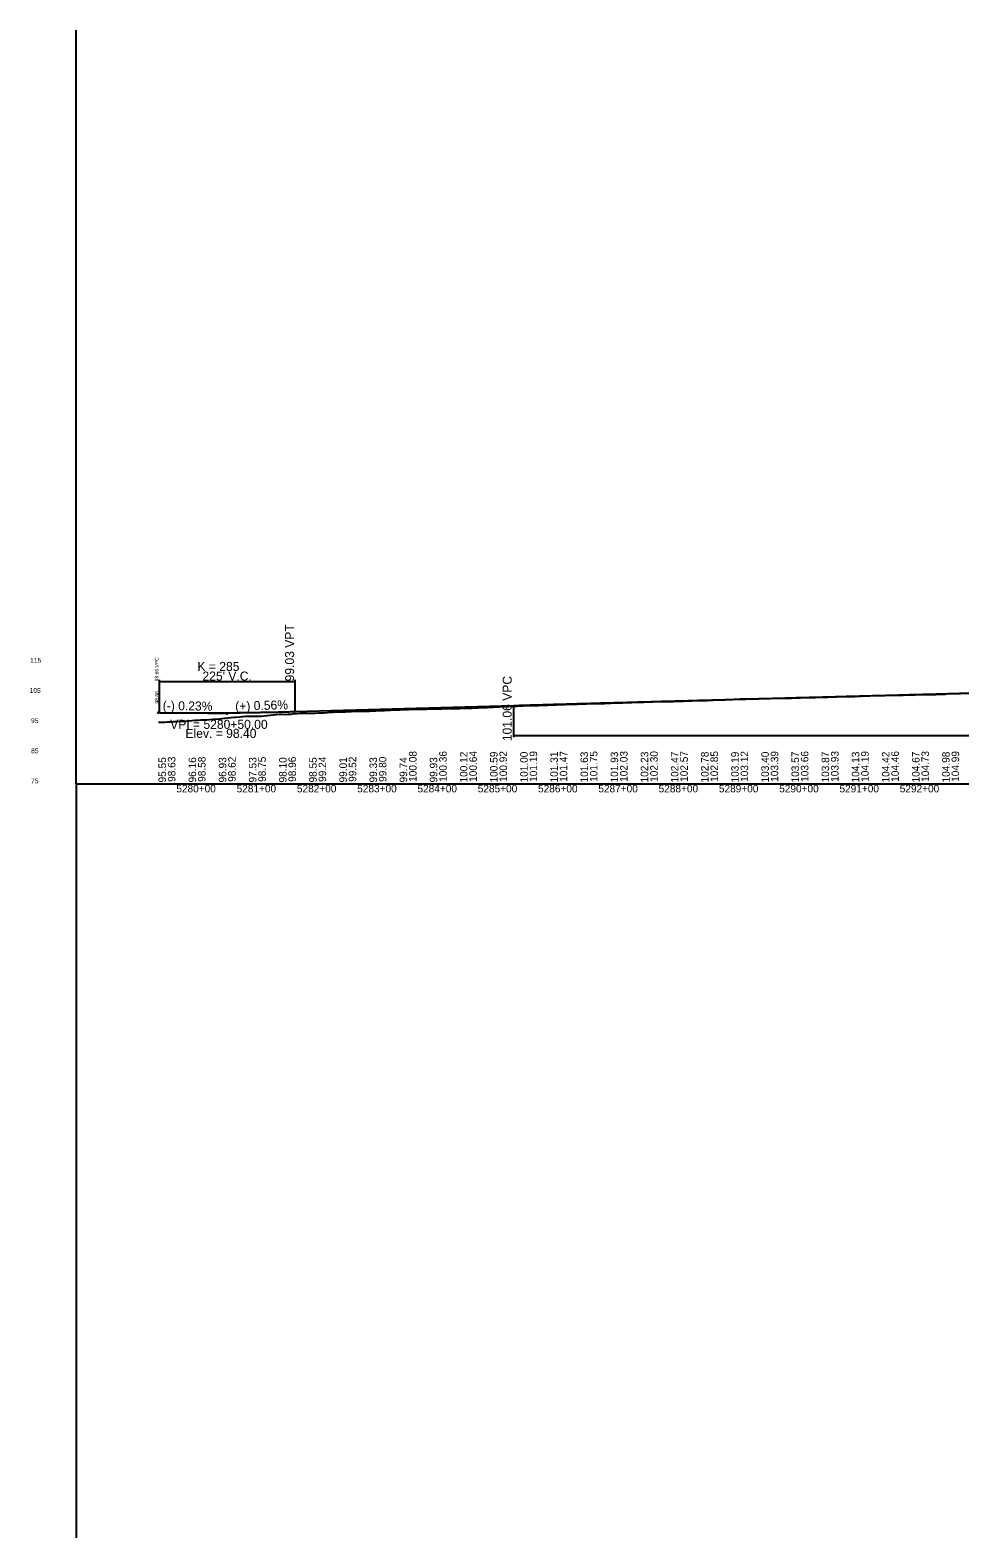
# Model space of a CAD drawing. Extents: x 2121671 to 2169879, y 557274 to 599957.
# Drawn here: x 2157292 to 2158834, y 591457 to 593957 of the extents above; entities that cross this region are included whole.
import ezdxf

# ---------------------------------------------------------------- set-up
doc = ezdxf.new("R2010")
doc.units = 0
for name, color, linetype in [('RD_DDB_ElevTX', 7, 'Continuous'), ('RD_DDB_GradeTX', 7, 'Continuous'), ('RD_DDB_Profile_EX', 7, 'Continuous'), ('RD_DDB_Profile_Lbl', 7, 'Continuous'), ('RD_DDB_Profile_PR', 7, 'Continuous'), ('RD_DDB_StaTX', 7, 'Continuous'), ('RD_DDB_StripGrade', 7, 'Continuous'), ('RD_DDB_VCLbl', 7, 'Continuous'), ('RD_GPK_Profile_Cell', 7, 'Continuous')]:
    doc.layers.add(name, color=color, linetype=linetype)

msp = doc.modelspace()

# ---------------------------------------------------------------- linework, layer by layer
at = {"layer": 'RD_DDB_GradeTX'}
for p, q in [((2157556.2, 592825.2), (2157617.2, 592824.5)), ((2157680.2, 592826.2), (2157619.2, 592824.5))]:
    msp.add_line(p, q, dxfattribs=at)
for centre in [(2157504.8, 592825.8), (2157618.2, 592824.5)]:
    msp.add_circle(centre, 1, dxfattribs=at)
at = {"layer": 'RD_DDB_Profile_EX'}
for points in [[(2158504.8, 592849.1), (2158509.8, 592849.2), (2158514.8, 592849.3), (2158519.8, 592849.5), (2158524.8, 592849.7), (2158529.8, 592849.8), (2158534.8, 592849.8), (2158539.8, 592849.8), (2158544.8, 592850), (2158549.8, 592850), (2158554.8, 592850), (2158559.8, 592850.1), (2158564.8, 592850.2), (2158569.8, 592850.4), (2158574.8, 592850.8), (2158579.8, 592850.9), (2158584.8, 592850.9), (2158589.8, 592851), (2158594.8, 592851.1), (2158599.8, 592851.3), (2158604.8, 592851.4), (2158609.8, 592851.5), (2158614.8, 592851.7), (2158619.8, 592851.9), (2158624.8, 592852), (2158629.8, 592852.2), (2158634.8, 592852.3), (2158639.8, 592852.4), (2158644.8, 592852.5), (2158649.8, 592852.6), (2158654.8, 592852.7), (2158659.8, 592852.8), (2158664.8, 592853), (2158669.8, 592853.2), (2158674.8, 592853.4), (2158679.8, 592853.5), (2158684.8, 592853.6), (2158689.8, 592854), (2158694.8, 592854.3), (2158699.8, 592854.5), (2158704.8, 592854.3), (2158709.8, 592854.4), (2158714.8, 592854.5), (2158719.8, 592854.6), (2158724.8, 592854.6), (2158729.8, 592854.8), (2158734.8, 592854.7), (2158739.8, 592855), (2158744.8, 592855.2), (2158749.8, 592855.1), (2158754.8, 592854.9), (2158759.8, 592855.3), (2158764.8, 592855.7), (2158769.8, 592855.9), (2158774.8, 592855.9), (2158779.8, 592856), (2158784.8, 592856), (2158789.8, 592856.1), (2158794.8, 592856.1), (2158799.8, 592856.2), (2158804.8, 592856.4), (2158809.8, 592856.5), (2158814.8, 592857.3), (2158819.8, 592857.4), (2158824.8, 592857.6), (2158829.8, 592857.7), (2158834.8, 592857.8)], [(2157504.8, 592810), (2157509.8, 592810.2), (2157514.8, 592810), (2157519.8, 592810.3), (2157524.8, 592810.6), (2157529.8, 592810.9), (2157534.8, 592811.2), (2157539.8, 592811.4), (2157544.8, 592811.5), (2157549.8, 592811.9), (2157554.8, 592812.2), (2157559.8, 592812.8), (2157564.8, 592813.1), (2157569.8, 592813.4), (2157574.8, 592813.7), (2157579.8, 592813.9), (2157584.8, 592814), (2157589.8, 592814.3), (2157594.8, 592814.9), (2157599.8, 592815.1), (2157604.8, 592815.5), (2157609.8, 592816.2), (2157614.8, 592816.9), (2157619.8, 592817.2), (2157624.8, 592817.6), (2157629.8, 592818.1), (2157634.8, 592818.4), (2157639.8, 592818.7), (2157644.8, 592819.4), (2157649.8, 592819.7), (2157654.8, 592819.9), (2157659.8, 592820), (2157664.8, 592820), (2157669.8, 592820.2), (2157674.8, 592820.2), (2157679.8, 592820.4), (2157684.8, 592821.1), (2157689.8, 592821.6), (2157694.8, 592822.1), (2157699.8, 592822.7), (2157704.8, 592823.2), (2157709.8, 592823), (2157714.8, 592822.9), (2157719.8, 592823), (2157724.8, 592823.5), (2157729.8, 592824.1), (2157734.8, 592824.5), (2157739.8, 592824.7), (2157744.8, 592824.8), (2157749.8, 592824.9), (2157754.8, 592825), (2157759.8, 592825), (2157764.8, 592825.1), (2157769.8, 592825.3), (2157774.8, 592825.4), (2157779.8, 592825.7), (2157784.8, 592826), (2157789.8, 592826.4), (2157794.8, 592826.6), (2157799.8, 592826.9), (2157804.8, 592827), (2157809.8, 592827.2), (2157814.8, 592827.4), (2157819.8, 592827.6), (2157824.8, 592827.8), (2157829.8, 592828), (2157834.8, 592828.2), (2157839.8, 592828.2), (2157844.8, 592828.3), (2157849.8, 592828.4), (2157854.8, 592828.5), (2157859.8, 592828.7), (2157864.8, 592829), (2157869.8, 592829.2), (2157874.8, 592829.4), (2157879.8, 592829.6), (2157884.8, 592829.7), (2157889.8, 592829.9), (2157894.8, 592830.2), (2157899.8, 592830.5), (2157904.8, 592830.7), (2157909.8, 592830.9), (2157914.8, 592831.1), (2157919.8, 592831.2), (2157924.8, 592831.4), (2157929.8, 592831.5), (2157934.8, 592831.5), (2157939.8, 592831.6), (2157944.8, 592831.6), (2157949.8, 592831.7), (2157954.8, 592831.9), (2157959.8, 592832), (2157964.8, 592832), (2157969.8, 592832.1), (2157974.8, 592832.3), (2157979.8, 592832.4), (2157984.8, 592832.3), (2157989.8, 592832.5), (2157994.8, 592832.6), (2157999.8, 592832.8), (2158004.8, 592832.8)], [(2158004.8, 592832.8), (2158009.8, 592833), (2158014.8, 592833), (2158019.8, 592833.1), (2158024.8, 592833.3), (2158029.8, 592833.6), (2158034.8, 592833.8), (2158039.8, 592834.1), (2158044.8, 592834.4), (2158049.8, 592834.5), (2158054.8, 592834.8), (2158059.8, 592835), (2158064.8, 592835.3), (2158069.8, 592835.5), (2158074.8, 592835.8), (2158079.8, 592836), (2158084.8, 592836.1), (2158089.8, 592836.4), (2158094.8, 592836.6), (2158099.8, 592836.8), (2158104.8, 592837), (2158109.8, 592837.2), (2158114.8, 592837.4), (2158119.8, 592837.5), (2158124.8, 592837.6), (2158129.8, 592837.8), (2158134.8, 592837.9), (2158139.8, 592838), (2158144.8, 592838.1), (2158149.8, 592838.3), (2158154.8, 592838.5), (2158159.8, 592838.7), (2158164.8, 592838.9), (2158169.8, 592839.1), (2158174.8, 592839.2), (2158179.8, 592839.4), (2158184.8, 592839.6), (2158189.8, 592839.7), (2158194.8, 592839.9), (2158199.8, 592840.1), (2158204.8, 592840.3), (2158209.8, 592840.4), (2158214.8, 592840.5), (2158219.8, 592840.7), (2158224.8, 592840.8), (2158229.8, 592840.9), (2158234.8, 592841), (2158239.8, 592841.1), (2158244.8, 592841.2), (2158249.8, 592841.4), (2158254.8, 592841.7), (2158259.8, 592841.9), (2158264.8, 592842), (2158269.8, 592842.2), (2158274.8, 592842.3), (2158279.8, 592842.4), (2158284.8, 592842.5), (2158289.8, 592842.8), (2158294.8, 592843), (2158299.8, 592843.1), (2158304.8, 592843.2), (2158309.8, 592843.4), (2158314.8, 592843.5), (2158319.8, 592843.7), (2158324.8, 592843.8), (2158329.8, 592844), (2158334.8, 592844), (2158339.8, 592844.1), (2158344.8, 592844.1), (2158349.8, 592844.1), (2158354.8, 592844.3), (2158359.8, 592844.5), (2158364.8, 592844.7), (2158369.8, 592844.8), (2158374.8, 592844.9), (2158379.8, 592845.1), (2158384.8, 592845.3), (2158389.8, 592845.6), (2158394.8, 592845.7), (2158399.8, 592845.7), (2158404.8, 592845.8), (2158409.8, 592845.9), (2158414.8, 592846.1), (2158419.8, 592846.5), (2158424.8, 592846.6), (2158429.8, 592846.8), (2158434.8, 592847), (2158439.8, 592847.2), (2158444.8, 592847.3), (2158449.8, 592847.4), (2158454.8, 592847.6), (2158459.8, 592847.9), (2158464.8, 592848.2), (2158469.8, 592848.5), (2158474.8, 592848.6), (2158479.8, 592848.6), (2158484.8, 592848.6), (2158489.8, 592848.8), (2158494.8, 592848.9), (2158499.8, 592849), (2158504.8, 592849.1)]]:
    msp.add_lwpolyline(points, dxfattribs=at)
at = {"layer": 'RD_DDB_Profile_PR'}
for p, q in [((2157504.8, 592825.8), (2157505.7, 592825.8)), ((2157730.7, 592827.6), (2158094.2, 592837.8))]:
    msp.add_line(p, q, dxfattribs=at)
for points in [[(2158094.2, 592837.8), (2158129.2, 592838.7), (2158164.2, 592839.7), (2158199.2, 592840.7), (2158234.2, 592841.7), (2158269.2, 592842.6), (2158304.2, 592843.6), (2158339.2, 592844.6), (2158374.2, 592845.5), (2158409.2, 592846.5), (2158444.2, 592847.4), (2158479.2, 592848.4), (2158514.2, 592849.3), (2158549.2, 592850.3), (2158584.2, 592851.2), (2158619.2, 592852.1), (2158654.2, 592853.1), (2158689.2, 592854), (2158724.2, 592854.9), (2158759.2, 592855.9), (2158794.2, 592856.8), (2158829.2, 592857.7), (2158864.2, 592858.6), (2158899.2, 592859.5), (2158934.2, 592860.5), (2158969.2, 592861.4), (2159004.2, 592862.3), (2159039.2, 592863.2), (2159074.2, 592864.1), (2159109.2, 592865), (2159144.2, 592865.9), (2159179.2, 592866.8), (2159214.2, 592867.7), (2159249.2, 592868.5), (2159284.2, 592869.4), (2159319.2, 592870.3), (2159354.2, 592871.2), (2159389.2, 592872.1), (2159424.2, 592873), (2159459.2, 592873.8), (2159494.2, 592874.7), (2159529.2, 592875.6), (2159564.2, 592876.4), (2159599.2, 592877.3), (2159634.2, 592878.1), (2159669.2, 592879), (2159704.2, 592879.9), (2159739.2, 592880.7), (2159774.2, 592881.6), (2159809.2, 592882.4), (2159844.2, 592883.2)], [(2157505.7, 592825.8), (2157510.2, 592825.7), (2157514.7, 592825.7), (2157519.2, 592825.6), (2157523.7, 592825.6), (2157528.2, 592825.6), (2157532.7, 592825.5), (2157537.2, 592825.5), (2157541.7, 592825.5), (2157546.2, 592825.4), (2157550.7, 592825.4), (2157555.2, 592825.4), (2157559.7, 592825.4), (2157564.2, 592825.4), (2157568.7, 592825.4), (2157573.2, 592825.4), (2157577.7, 592825.4), (2157582.2, 592825.4), (2157586.7, 592825.4), (2157591.2, 592825.4), (2157595.7, 592825.4), (2157600.2, 592825.5), (2157604.7, 592825.5), (2157609.2, 592825.5), (2157613.7, 592825.5), (2157618.2, 592825.6), (2157622.7, 592825.6), (2157627.2, 592825.7), (2157631.7, 592825.7), (2157636.2, 592825.8), (2157640.7, 592825.8), (2157645.2, 592825.9), (2157649.7, 592825.9), (2157654.2, 592826), (2157658.7, 592826.1), (2157663.2, 592826.1), (2157667.7, 592826.2), (2157672.2, 592826.3), (2157676.7, 592826.4), (2157681.2, 592826.4), (2157685.7, 592826.5), (2157690.2, 592826.6), (2157694.7, 592826.7), (2157699.2, 592826.8), (2157703.7, 592826.9), (2157708.2, 592827), (2157712.7, 592827.1), (2157717.2, 592827.3), (2157721.7, 592827.4), (2157726.2, 592827.5), (2157730.7, 592827.6)]]:
    msp.add_spline(points, degree=3, dxfattribs=at)
at = {"layer": 'RD_DDB_VCLbl'}
for p, q in [((2157505.7, 592880.1), (2157505.7, 592825.8)), ((2157505.7, 592877.6), (2157730.7, 592877.6)), ((2157730.7, 592880.1), (2157730.7, 592827.6)), ((2158094.2, 592785.3), (2158094.2, 592837.8)), ((2158094.2, 592787.8), (2159844.2, 592787.8))]:
    msp.add_line(p, q, dxfattribs=at)
at = {"layer": 'RD_GPK_Profile_Cell'}
for q in [(2157368.2, 593957.5), (2160568.2, 592707.5), (2157368.2, 591457.5)]:
    msp.add_line((2157368.2, 592707.5), q, dxfattribs=at)

# ---------------------------------------------------------------- texts
at = {"layer": 'RD_DDB_ElevTX'}
for s, p in [('115', (2157291.8, 592908.5)), ('105', (2157291, 592858.5)), ('95', (2157293.4, 592808.5)), ('85', (2157293.4, 592758.5)), ('75', (2157293.4, 592708.5))]:
    msp.add_text(s, height=8, dxfattribs=at).set_placement(p)
at = {"layer": 'RD_DDB_GradeTX'}
for s, rotation, p in [('(-) 0.23%', 359.3411, (2157511.7, 592830)), ('(+) 0.56%', 1.6002, (2157632.2, 592829))]:
    msp.add_text(s, height=15, rotation=rotation, dxfattribs=at).set_placement(p)
at = {"layer": 'RD_DDB_Profile_Lbl'}
msp.add_text('98.66', height=6, rotation=90, dxfattribs=at).set_placement((2157504.8, 592840.8))
for s, p in [('VPI = 5280+50.00', (2157524.1, 592798.9)), ('Elev. = 98.40', (2157549.5, 592783.9))]:
    msp.add_text(s, height=15, dxfattribs=at).set_placement(p)
at = {"layer": 'RD_DDB_StaTX'}
for s, p in [('5280+00', (2157534.3, 592693.6)), ('5281+00', (2157634.3, 592693.6)), ('5282+00', (2157734.3, 592693.6)), ('5283+00', (2157834.3, 592693.6)), ('5284+00', (2157934.3, 592693.6)), ('5285+00', (2158034.3, 592693.6)), ('5286+00', (2158134.3, 592693.6)), ('5287+00', (2158234.3, 592693.6)), ('5288+00', (2158334.3, 592693.6)), ('5289+00', (2158434.3, 592693.6)), ('5290+00', (2158534.3, 592693.6)), ('5291+00', (2158634.3, 592693.6)), ('5292+00', (2158734.3, 592693.6))]:
    msp.add_text(s, height=12.5, dxfattribs=at).set_placement(p)
at = {"layer": 'RD_DDB_StripGrade'}
for s, height, p in [('99.03 VPT', 15, (2157729.7, 592877.6)), ('98.66 VPC', 6, (2157504.7, 592877.6)), ('101.06 VPC', 15, (2158090.6, 592778.5)), ('95.55', 12.5, (2157517.2, 592710)), ('98.63', 12.5, (2157532.8, 592711)), ('96.16', 12.5, (2157567.2, 592710)), ('98.58', 12.5, (2157582.8, 592711)), ('96.93', 12.5, (2157617.2, 592710)), ('98.62', 12.5, (2157632.8, 592711)), ('97.53', 12.5, (2157667.2, 592710)), ('98.75', 12.5, (2157682.8, 592711)), ('98.10', 12.5, (2157717.2, 592710)), ('98.96', 12.5, (2157732.8, 592711)), ('98.55', 12.5, (2157767.2, 592710)), ('99.24', 12.5, (2157782.8, 592711)), ('99.01', 12.5, (2157817.2, 592710)), ('99.52', 12.5, (2157832.8, 592711)), ('99.33', 12.5, (2157867.2, 592710)), ('99.80', 12.5, (2157882.8, 592711)), ('99.74', 12.5, (2157917.2, 592710)), ('100.08', 12.5, (2157932.8, 592711)), ('99.93', 12.5, (2157967.2, 592710)), ('100.36', 12.5, (2157982.8, 592711)), ('100.12', 12.5, (2158017.2, 592710)), ('100.64', 12.5, (2158032.8, 592711)), ('100.59', 12.5, (2158067.2, 592710)), ('100.92', 12.5, (2158082.8, 592711)), ('101.00', 12.5, (2158117.2, 592710)), ('101.19', 12.5, (2158132.8, 592711)), ('101.31', 12.5, (2158167.2, 592710)), ('101.47', 12.5, (2158182.8, 592711)), ('101.63', 12.5, (2158217.2, 592710)), ('101.75', 12.5, (2158232.8, 592711)), ('101.93', 12.5, (2158267.2, 592710)), ('102.03', 12.5, (2158282.8, 592711)), ('102.23', 12.5, (2158317.2, 592710)), ('102.30', 12.5, (2158332.8, 592711)), ('102.47', 12.5, (2158367.2, 592710)), ('102.57', 12.5, (2158382.8, 592711)), ('102.78', 12.5, (2158417.2, 592710)), ('102.85', 12.5, (2158432.8, 592711)), ('103.19', 12.5, (2158467.2, 592710)), ('103.12', 12.5, (2158482.8, 592711)), ('103.40', 12.5, (2158517.2, 592710)), ('103.39', 12.5, (2158532.8, 592711)), ('103.57', 12.5, (2158567.2, 592710)), ('103.66', 12.5, (2158582.8, 592711)), ('103.87', 12.5, (2158617.2, 592710)), ('103.93', 12.5, (2158632.8, 592711)), ('104.13', 12.5, (2158667.2, 592710)), ('104.19', 12.5, (2158682.8, 592711)), ('104.42', 12.5, (2158717.2, 592710)), ('104.46', 12.5, (2158732.8, 592711)), ('104.67', 12.5, (2158767.2, 592710)), ('104.73', 12.5, (2158782.8, 592711)), ('104.98', 12.5, (2158817.2, 592710)), ('104.99', 12.5, (2158832.8, 592711))]:
    msp.add_text(s, height=height, rotation=90, dxfattribs=at).set_placement(p)
at = {"layer": 'RD_DDB_VCLbl'}
for s, p in [('K = 285', (2157569.3, 592894.9)), ("225' V.C.", (2157577.7, 592878.9))]:
    msp.add_text(s, height=15, dxfattribs=at).set_placement(p)
at = {"layer": 'RD_GPK_Profile_Cell'}
for s, p in [('I95', (2157368.2, 592711.8)), ('P_C_SBSPLIT2', (2157368.2, 592711.2)), ('527800.000000', (2157368.2, 592710.6)), ('75', (2157368.2, 592710)), ('50', (2157368.2, 592709.3)), ('10', (2157368.2, 592708.7)), ('NOGAP', (2157368.2, 592708.1))]:
    msp.add_text(s, height=0.208, dxfattribs=at).set_placement(p)

doc.saveas('drawing.dxf')
